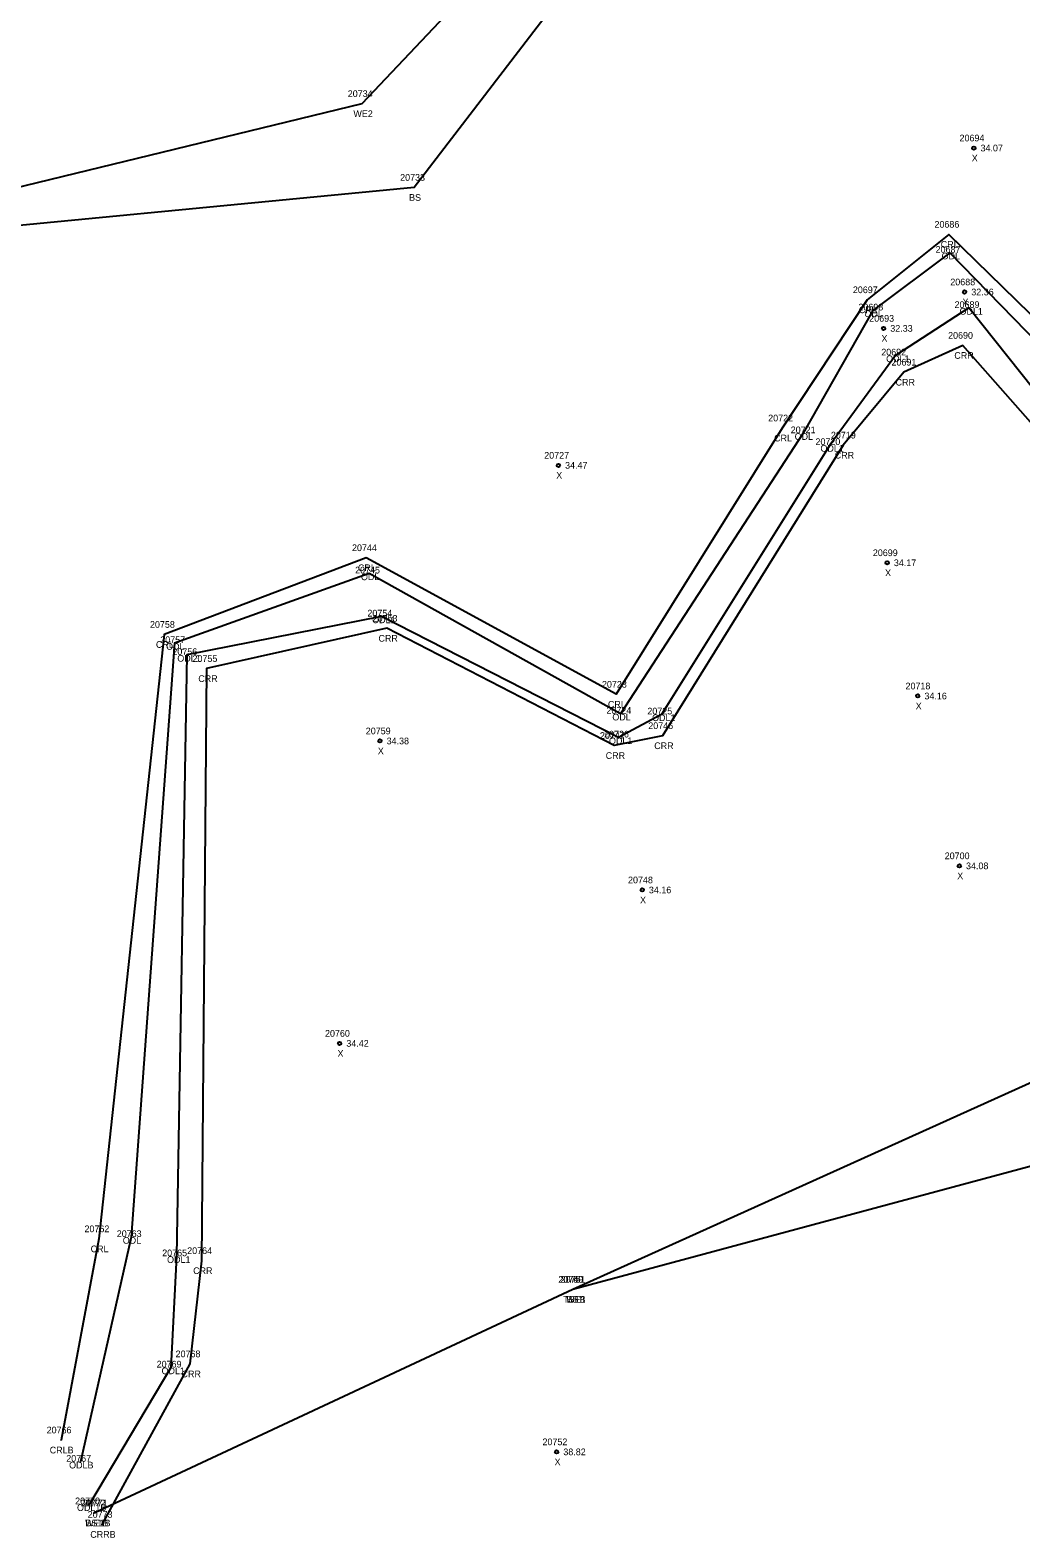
# Model space of a CAD drawing. Extents: x 2445178 to 2446260, y 791158 to 792318.
# Drawn here: x 2445282.6 to 2445430.8, y 791555.1 to 791780.8 of the extents above; entities that cross this region are included whole.
import ezdxf

# ---------------------------------------------------------------- set-up
doc = ezdxf.new("R2010")
doc.units = 0
for name, color, linetype in [('RD_DTM_BkLn2', 7, 'Continuous'), ('RD_EX_H2O', 7, 'Continuous'), ('RD_EX_H2O_txCode', 7, 'Continuous'), ('RD_Sketch8', 7, 'Continuous'), ('RD_SMD_Locator', 7, 'Continuous'), ('RD_SMD_Misc', 7, 'Continuous')]:
    doc.layers.add(name, color=color, linetype=linetype)

msp = doc.modelspace()

# ---------------------------------------------------------------- linework, layer by layer
at = {"layer": 'RD_DTM_BkLn2'}
for points in [[(2445394.99, 791911.52), (2445386.85, 791818.37), (2445340.06, 791757.26), (2445258.15, 791749.35), (2445179.64, 791718.55)], [(2445612.18, 791734.98), (2445557.56, 791698.84), (2445552.02, 791673.05), (2445513.68, 791664.7), (2445463.32, 791637.22), (2445363.77, 791592.3), (2445292.26, 791558.82)], [(2445612.18, 791734.98), (2445563.15, 791688.49), (2445558.95, 791665.85), (2445520.9, 791652.98), (2445473.7, 791621.85), (2445363.77, 791592.3)]]:
    msp.add_lwpolyline(points, dxfattribs=at)
at = {"layer": 'RD_EX_H2O'}
for points in [[(2445390.88, 791910.3), (2445382.88, 791823.37), (2445332.21, 791769.8), (2445259.4, 791752.08), (2445179.59, 791723.55)], [(2445748.32, 791780.49), (2445701.12, 791774.43), (2445677.09, 791767.59), (2445662.39, 791761.56), (2445644.36, 791766.93), (2445623.55, 791762.71), (2445618.49, 791746.46), (2445607.67, 791748.78), (2445606.64, 791748.27), (2445612.18, 791734.98), (2445561.56, 791692.97), (2445554.1, 791670.89), (2445517.8, 791656.91), (2445473.7, 791621.85), (2445363.77, 791592.3), (2445292.26, 791558.82)], [(2445598, 791771), (2445580.58, 791766.25), (2445545.35, 791747.76), (2445529.9, 791743.48), (2445493.64, 791702.86), (2445469.99, 791696.32), (2445420.2, 791747.49), (2445408.65, 791738.85), (2445398.22, 791720.47), (2445370.93, 791678.47), (2445333.32, 791699.47), (2445304.17, 791689.05), (2445297.68, 791600.13), (2445290.12, 791566.49)], [(2445600.16, 791766.47), (2445586.11, 791757.06), (2445543.42, 791738.09), (2445500.69, 791690.42), (2445463.87, 791687.89), (2445423.05, 791739.22), (2445412.07, 791732.11), (2445402.24, 791718.7), (2445377.05, 791678.37), (2445370.6, 791674.92), (2445335.15, 791693.03), (2445306.01, 791687.27), (2445304.48, 791597.26), (2445303.65, 791580.6), (2445291.47, 791560.13)], [(2445601.06, 791763.87), (2445588.04, 791754.39), (2445544.11, 791733.92), (2445501.1, 791687.67), (2445464.95, 791685.09), (2445422.11, 791733.61), (2445413.32, 791729.6), (2445404.23, 791718.68), (2445377.21, 791675.18), (2445369.95, 791673.71), (2445335.95, 791691.26), (2445308.99, 791685.23), (2445308.22, 791596.59), (2445306.48, 791581.14), (2445293.31, 791557.11)], [(2445530.12, 791747.41), (2445491.74, 791707.13), (2445470.74, 791700.73), (2445420.06, 791750.24), (2445407.82, 791740.44), (2445395.12, 791721.24), (2445370.26, 791681.38), (2445332.86, 791701.82), (2445302.63, 791690.34), (2445292.86, 791599.86), (2445287.21, 791569.74)]]:
    msp.add_lwpolyline(points, dxfattribs=at)
at = {"layer": 'RD_SMD_Locator'}
for centre, radius in [((2445332.21, 791769.8), 0.001), ((2445423.78, 791763.16), 0.25), ((2445340.06, 791757.26), 0.001), ((2445420.06, 791750.24), 0.001), ((2445420.2, 791747.49), 0.001), ((2445422.4, 791741.61), 0.25), ((2445407.82, 791740.44), 0.001), ((2445408.65, 791738.85), 0.001), ((2445423.05, 791739.22), 0.001), ((2445410.28, 791736.16), 0.25), ((2445412.07, 791732.11), 0.001), ((2445422.11, 791733.61), 0.001), ((2445413.32, 791729.6), 0.001), ((2445395.12, 791721.24), 0.001), ((2445398.22, 791720.47), 0.001), ((2445402.24, 791718.7), 0.001), ((2445404.23, 791718.68), 0.001), ((2445361.62, 791715.66), 0.25), ((2445332.86, 791701.82), 0.001), ((2445410.81, 791701.07), 0.25), ((2445333.32, 791699.47), 0.001), ((2445335.15, 791693.03), 0.001), ((2445335.95, 791691.26), 0.001), ((2445302.63, 791690.34), 0.001), ((2445304.17, 791689.05), 0.001), ((2445306.01, 791687.27), 0.001), ((2445308.99, 791685.23), 0.001), ((2445370.26, 791681.38), 0.001), ((2445415.39, 791681.13), 0.25), ((2445370.93, 791678.47), 0.001), ((2445377.05, 791678.37), 0.001), ((2445334.92, 791674.4), 0.25), ((2445369.95, 791673.71), 0.001), ((2445370.6, 791674.92), 0.001), ((2445377.21, 791675.18), 0.001), ((2445421.61, 791655.7), 0.25), ((2445374.16, 791652.09), 0.25), ((2445328.89, 791629.12), 0.25), ((2445292.86, 791599.86), 0.001), ((2445297.68, 791600.13), 0.001), ((2445304.48, 791597.26), 0.001), ((2445308.22, 791596.59), 0.001), ((2445363.77, 791592.3), 0.001), ((2445363.77, 791592.3), 0.001), ((2445363.77, 791592.3), 0.001), ((2445303.65, 791580.6), 0.001), ((2445306.48, 791581.14), 0.001), ((2445287.21, 791569.74), 0.001), ((2445361.36, 791567.97), 0.25), ((2445290.12, 791566.49), 0.001), ((2445291.47, 791560.13), 0.001), ((2445292.26, 791558.82), 0.001), ((2445292.26, 791558.82), 0.001), ((2445293.31, 791557.11), 0.001)]:
    msp.add_circle(centre, radius, dxfattribs=at)

# ---------------------------------------------------------------- texts
at = {"layer": 'RD_EX_H2O_txCode'}
for s, p in [('20734', (2445330.1, 791770.8)), ('WE2', (2445330.95, 791767.8)), ('20686', (2445417.89, 791751.24)), ('20687', (2445418.06, 791747.49)), ('CRL', (2445418.83, 791748.24)), ('ODL', (2445418.96, 791746.49)), ('20697', (2445405.68, 791741.44)), ('20698', (2445406.51, 791738.85)), ('CRL', (2445406.59, 791738.44)), ('ODL', (2445407.41, 791737.85)), ('20689', (2445420.9, 791739.22)), ('ODL1', (2445421.64, 791738.22)), ('20690', (2445419.93, 791734.61)), ('20692', (2445409.93, 791732.11)), ('ODL1', (2445410.66, 791731.11)), ('CRR', (2445420.86, 791731.61)), ('20691', (2445411.46, 791730.6)), ('CRR', (2445412.07, 791727.6)), ('20722', (2445393.01, 791722.24)), ('20721', (2445396.38, 791720.47)), ('20719', (2445402.39, 791719.68)), ('CRL', (2445393.9, 791719.24)), ('ODL', (2445396.97, 791719.47)), ('20720', (2445400.08, 791718.7)), ('ODL1', (2445400.83, 791717.7)), ('CRR', (2445402.97, 791716.68)), ('20744', (2445330.74, 791702.82)), ('20745', (2445331.2, 791699.47)), ('CRL', (2445331.63, 791699.82)), ('ODL', (2445332.08, 791698.47)), ('20754', (2445333.04, 791693.03)), ('20758', (2445300.51, 791691.34)), ('ODL1', (2445333.75, 791692.03)), ('20753', (2445333.83, 791692.26)), ('CRL', (2445301.4, 791688.34)), ('20757', (2445302.05, 791689.05)), ('ODL', (2445302.92, 791688.05)), ('CRR', (2445334.7, 791689.26)), ('20756', (2445303.86, 791687.27)), ('ODL1', (2445304.6, 791686.27)), ('20755', (2445306.87, 791686.23)), ('CRR', (2445307.74, 791683.23)), ('20723', (2445368.14, 791682.38)), ('CRL', (2445369.03, 791679.38)), ('20724', (2445368.81, 791678.47)), ('ODL', (2445369.69, 791677.47)), ('20725', (2445374.93, 791678.37)), ('ODL1', (2445375.64, 791677.37)), ('20747', (2445367.83, 791674.71)), ('20726', (2445368.45, 791674.92)), ('20746', (2445375.07, 791676.18)), ('ODL1', (2445369.19, 791673.92)), ('CRR', (2445375.96, 791673.18)), ('CRR', (2445368.7, 791671.71)), ('20762', (2445290.71, 791600.86)), ('20763', (2445295.54, 791600.13)), ('CRL', (2445291.63, 791597.86)), ('ODL', (2445296.44, 791599.13)), ('20765', (2445302.34, 791597.26)), ('ODL1', (2445303.07, 791596.26)), ('20764', (2445306.08, 791597.59)), ('CRR', (2445306.97, 791594.59)), ('20749', (2445361.65, 791593.3)), ('WE1', (2445362.79, 791590.3)), ('20768', (2445304.34, 791582.14)), ('20769', (2445301.51, 791580.6)), ('ODL1', (2445302.24, 791579.6)), ('CRR', (2445305.23, 791579.14)), ('20766', (2445285.05, 791570.74)), ('CRLB', (2445285.51, 791567.74)), ('20767', (2445287.98, 791566.49)), ('ODLB', (2445288.41, 791565.49)), ('20770', (2445289.31, 791560.13)), ('20771', (2445290.43, 791559.82)), ('ODL1B', (2445289.59, 791559.13)), ('20773', (2445291.19, 791558.11)), ('WE1B', (2445290.81, 791556.82)), ('CRRB', (2445291.58, 791555.11))]:
    msp.add_text(s, height=1, dxfattribs=at).set_placement(p)
at = {"layer": 'RD_Sketch8'}
for s, p in [('20694', (2445421.64, 791764.16)), ('34.07', (2445424.78, 791762.66)), ('X', (2445423.47, 791761.16)), ('20688', (2445420.26, 791742.61)), ('32.36', (2445423.4, 791741.11)), ('X', (2445422.09, 791739.61)), ('20693', (2445408.13, 791737.16)), ('32.33', (2445411.28, 791735.66)), ('X', (2445409.96, 791734.16)), ('20727', (2445359.5, 791716.66)), ('34.47', (2445362.62, 791715.16)), ('X', (2445361.3, 791713.66)), ('20699', (2445408.67, 791702.07)), ('34.17', (2445411.81, 791700.57)), ('X', (2445410.5, 791699.07)), ('20718', (2445413.56, 791682.13)), ('X', (2445415.08, 791679.13)), ('34.16', (2445416.39, 791680.63)), ('20759', (2445332.8, 791675.4)), ('X', (2445334.6, 791672.4)), ('34.38', (2445335.92, 791673.9)), ('20700', (2445419.42, 791656.7)), ('34.08', (2445422.61, 791655.2)), ('20748', (2445372.04, 791653.09)), ('X', (2445421.3, 791653.7)), ('X', (2445373.84, 791650.09)), ('34.16', (2445375.16, 791651.59)), ('20760', (2445326.7, 791630.12)), ('X', (2445328.57, 791627.12)), ('34.42', (2445329.89, 791628.62)), ('20752', (2445359.24, 791568.97)), ('38.82', (2445362.36, 791567.47)), ('X', (2445361.05, 791565.97))]:
    msp.add_text(s, height=1, dxfattribs=at).set_placement(p)
at = {"layer": 'RD_SMD_Misc'}
for s, p in [('20733', (2445337.94, 791758.26)), ('BS', (2445339.28, 791755.26)), ('20750', (2445361.61, 791593.3)), ('20751', (2445361.94, 791593.3)), ('TS1B', (2445362.34, 791590.3)), ('BS1', (2445362.83, 791590.3)), ('20772', (2445290.15, 791559.82)), ('BS1B', (2445290.85, 791556.82))]:
    msp.add_text(s, height=1, dxfattribs=at).set_placement(p)

doc.saveas('drawing.dxf')
